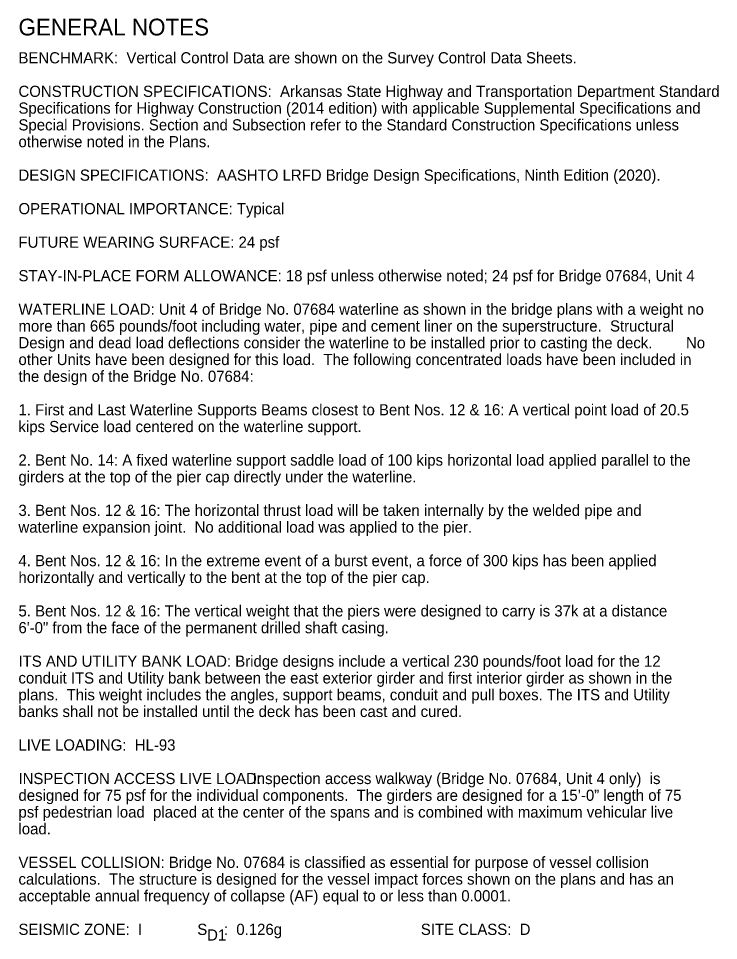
# Model space of a CAD drawing. Extents: x 0.06 to 1.36, y 0.04 to 0.88.
# Drawn here: x 0.0907 to 0.4039, y 0.468 to 0.8806 of the extents above; entities that cross this region are included whole.
import ezdxf

# ---------------------------------------------------------------- set-up
doc = ezdxf.new("R2010")
doc.units = 0
doc.layers.add('B_Boring Annot', color=7, linetype='Continuous')
doc.layers.add('R_ROW', color=7, linetype='Continuous')

msp = doc.modelspace()

# ---------------------------------------------------------------- texts
at = {"layer": 'B_Boring Annot'}
for s, p in [('BENCHMARK:  Vertical Control Data are shown on the Survey Control Data Sheets.', (0.09071, 0.86052)), ('CONSTRUCTION SPECIFICATIONS:  Arkansas State Highway and Transportation Department Standard ', (0.09071, 0.84552)), ('Specifications for Highway Construction (2014 edition) with applicable Supplemental Specifications and ', (0.09071, 0.83802)), ('Special Provisions. Section and Subsection refer to the Standard Construction Specifications unless ', (0.09071, 0.83052)), ('otherwise noted in the Plans.', (0.09071, 0.82302)), ('DESIGN SPECIFICATIONS:  AASHTO LRFD Bridge Design Specifications, Ninth Edition (2020).', (0.09071, 0.80802)), ('OPERATIONAL IMPORTANCE: Typical', (0.09071, 0.79302)), ('FUTURE WEARING SURFACE: 24 psf', (0.09071, 0.77802)), ('STAY-IN-PLACE FORM ALLOWANCE: 18 psf unless otherwise noted; 24 psf for Bridge 07684, Unit 4 ', (0.09071, 0.76302)), ('WATERLINE LOAD: Unit 4 of Bridge No. 07684 waterline as shown in the bridge plans with a weight no ', (0.09071, 0.74802)), ('more than 665 pounds/foot including water, pipe and cement liner on the superstructure.  Structural ', (0.09071, 0.74052)), ('Design and dead load deflections consider the waterline to be installed prior to casting the deck.  ', (0.09071, 0.73302)), (' No ', (0.38747, 0.73302)), ('other Units have been designed for this load.  The following concentrated loads have been included in ', (0.09071, 0.72552)), ('the design of the Bridge No. 07684:  ', (0.09071, 0.71802)), ('1. First and Last Waterline Supports Beams closest to Bent Nos. 12 & 16: A vertical point load of 20.5 ', (0.09071, 0.70302)), ('kips Service load centered on the waterline support.', (0.09071, 0.69552)), ('2. Bent No. 14: A fixed waterline support saddle load of 100 kips horizontal load applied parallel to the ', (0.09071, 0.68052)), ('girders at the top of the pier cap directly under the waterline.', (0.09071, 0.67302)), ('3. Bent Nos. 12 & 16: The horizontal thrust load will be taken internally by the welded pipe and ', (0.09071, 0.65802)), ('waterline expansion joint.  No additional load was applied to the pier.', (0.09071, 0.65052)), ('4. Bent Nos. 12 & 16: In the extreme event of a burst event, a force of 300 kips has been applied ', (0.09071, 0.63552)), ('horizontally and vertically to the bent at the top of the pier cap. ', (0.09071, 0.62802)), ('5. Bent Nos. 12 & 16: The vertical weight that the piers were designed to carry is 37k at a distance ', (0.09071, 0.61302)), ('6\'-0" from the face of the permanent drilled shaft casing.', (0.09071, 0.60552)), ('ITS AND UTILITY BANK LOAD: Bridge designs include a vertical 230 pounds/foot load for the 12 ', (0.09071, 0.59052)), ('conduit ITS and Utility bank between the east exterior girder and first interior girder as shown in the ', (0.09071, 0.58302)), ('plans.  This weight includes the angles, support beams, conduit and pull boxes. The ITS and Utility ', (0.09071, 0.57552)), ('banks shall not be installed until the deck has been cast and cured.  ', (0.09071, 0.56802)), ('LIVE LOADING:  HL-93', (0.09071, 0.55302)), ('INSPECTION ACCESS LIVE LOAD: ', (0.09071, 0.53802)), ('Inspection access walkway (Bridge No. 07684, Unit 4 only)  is ', (0.19545, 0.53802)), ('designed for 75 psf for the individual components.  The girders are designed for a 15’-0” length of 75 ', (0.09071, 0.53052)), ('psf pedestrian load  placed at the center of the spans and is combined with maximum vehicular live ', (0.09071, 0.52302)), ('load.', (0.09071, 0.51552)), ('VESSEL COLLISION: Bridge No. 07684 is classified as essential for purpose of vessel collision ', (0.09071, 0.50052)), ('calculations.  The structure is designed for the vessel impact forces shown on the plans and has an ', (0.09071, 0.49302)), ('acceptable annual frequency of collapse (AF) equal to or less than 0.0001.', (0.09071, 0.48552)), ('SEISMIC ZONE:  I', (0.09071, 0.47052)), ('S    :  0.126g', (0.17071, 0.47052)), ('SITE CLASS:  D', (0.27071, 0.47052)), ('D1', (0.17511, 0.468))]:
    msp.add_text(s, height=0.005, dxfattribs=at).set_placement(p)
at = {"layer": 'R_ROW'}
msp.add_text('GENERAL NOTES', height=0.0075, dxfattribs=at).set_placement((0.09071, 0.87302))

doc.saveas('drawing.dxf')
